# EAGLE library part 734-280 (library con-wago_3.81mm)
Serie 734, Stiftleiste (für Leiterplatten) Einlötstift abgewinkelt 1 x 1 mm / Series 734, Male header (for PCBs) Angled solder pin 1 x 1 mm Polzahl / Pole No.: 20 Rastermaß / Pitch: 3.81 mm Bemessungsspannung / Rated Voltage: 160 V Nennstrom / Nominal Current: 10 A Lötstiftlänge: / Solder Pin Length: 3.8 mm Farbe / Color: orange / orange Stand: 01.01.2012. Die jeweils aktuellen Daten zu diesem Artikel finden Sie in unserem Produktkatalog, den Sie unter www.wago.com einsehen können. As of: 01/01/2012. Please find the newest data for this article in our product catalogue, which can be viewed under www.wago.com.
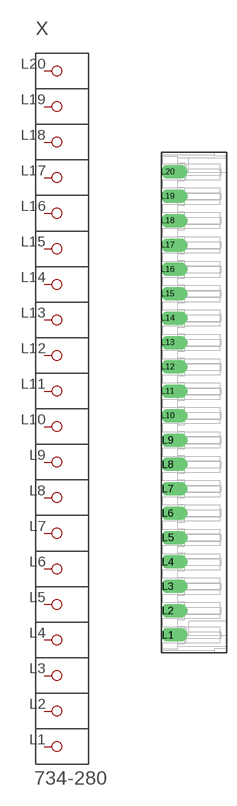
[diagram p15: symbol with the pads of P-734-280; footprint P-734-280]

Designator prefix X

## 734-280  [P-734-280]
L1  P1
L2  P2
L3  P3
L4  P4
L5  P5
L6  P6
L7  P7
L8  P8
L9  P9
L10  P10
L11  P11
L12  P12
L13  P13
L14  P14
L15  P15
L16  P16
L17  P17
L18  P18
L19  P19
L20  P20

## Footprint P-734-280 (pad centres in mm)
drill 1.4 pad 2 offset: L1 -4.15,-36.345; L2 -4.15,-32.535; L3 -4.15,-28.725; L4 -4.15,-24.915; L5 -4.15,-21.105; L6 -4.15,-17.295; L7 -4.15,-13.485; L8 -4.15,-9.675; L9 -4.15,-5.865; L10 -4.15,-2.055; L11 -4.15,1.755; L12 -4.15,5.565; L13 -4.15,9.375; L14 -4.15,13.185; L15 -4.15,16.995; L16 -4.15,20.805; L17 -4.15,24.615; L18 -4.15,28.425; L19 -4.15,32.235; L20 -4.15,36.045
